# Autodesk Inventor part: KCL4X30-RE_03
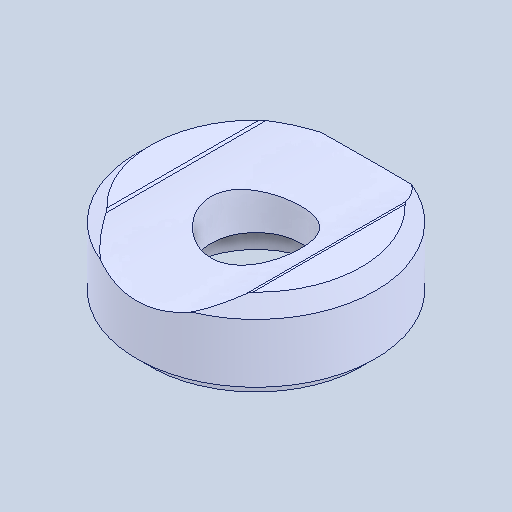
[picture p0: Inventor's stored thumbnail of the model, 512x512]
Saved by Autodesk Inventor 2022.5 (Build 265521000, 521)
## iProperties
Created: 2024-08
Part Number: KCL4X30-RE_03
Material: 一般
Document SubType Name: Modeling
Designer: ImaoCorp
Density: 1 g/cm^3
Appearance: 既定
Author: ImaoCorp
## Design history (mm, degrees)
feature "KCL4X30-RE_03"
node "ソリッド1"
